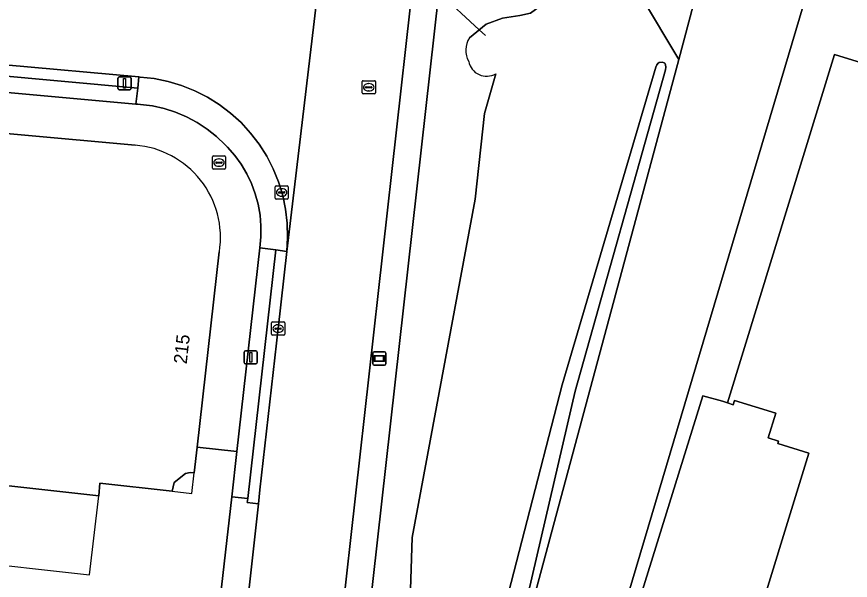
# Model space of a CAD drawing. Extents: x 161385 to 162589, y 388479 to 389756.
# Drawn here: x 162330.1 to 162393.2, y 388816.9 to 388859.6 of the extents above; entities that cross this region are included whole.
import ezdxf

# ---------------------------------------------------------------- set-up
doc = ezdxf.new("R2010")
doc.units = 0
for name, color, linetype in [('IMGEO_Berm_groen', 7, 'Continuous'), ('IMGEO_Duiker', 7, 'Continuous'), ('IMGEO_Erf', 7, 'Continuous'), ('IMGEO_Groenvoorziening', 7, 'Continuous'), ('IMGEO_Kolk', 7, 'Continuous'), ('IMGEO_Lichtmast', 7, 'Continuous'), ('IMGEO_Oever', 7, 'Continuous'), ('IMGEO_Pand', 7, 'Continuous'), ('IMGEO_Pand_nummerreeks', 7, 'Continuous'), ('IMGEO_Pand_overbouw', 7, 'Continuous'), ('IMGEO_Parkeervlak_open', 7, 'Continuous'), ('IMGEO_Rijbaan_lokaal_gesloten', 7, 'Continuous'), ('IMGEO_Rioolput', 7, 'Continuous'), ('IMGEO_Voetpad_open', 7, 'Continuous'), ('IMGEO_Waterloop', 7, 'Continuous'), ('IMGEO_Wegwijzer', 7, 'Continuous')]:
    doc.layers.add(name, color=color, linetype=linetype)

msp = doc.modelspace()

# ---------------------------------------------------------------- linework, layer by layer
at = {"layer": 'IMGEO_Berm_groen'}
for points in [[(162288.732, 388859.544), (162288.662, 388858.772), (162339.281, 388854.162), (162339.344, 388854.997)], [(162349.892, 388835.959), (162350.544, 388841.795), (162349.725, 388841.919), (162347.59, 388823.099), (162347.556, 388822.796), (162348.397, 388822.686), (162348.515, 388823.765)]]:
    msp.add_lwpolyline(points, close=True, dxfattribs=at)
at = {"layer": 'IMGEO_Duiker'}
msp.add_lwpolyline([(162365.584, 388858.13), (162365.112, 388858.568), (162362.048, 388861.405), (162360.956, 388862.417), (162360.209, 388863.109), (162355.382, 388867.663), (162353.656, 388867.925), (162352.651, 388868.077), (162346.541, 388869.005), (162345.729, 388869.128)], dxfattribs=at)
at = {"layer": 'IMGEO_Erf'}
for points in [[(162346.379, 388823.232), (162346.766, 388826.65), (162343.766, 388826.99), (162343.546, 388825.042), (162343.228, 388825.075), (162342.869, 388824.995), (162342.013, 388824.299), (162341.857, 388823.664), (162336.398, 388824.261), (162336.306, 388823.293), (162323.575, 388824.702)], [(162344.428, 388805.878), (162344.552, 388807.124), (162346.379, 388823.232)]]:
    msp.add_lwpolyline(points, dxfattribs=at)
at = {"layer": 'IMGEO_Groenvoorziening'}
for points in [[(162383.901, 388870.224), (162364.588, 388875.934), (162363.642, 388871.781), (162362.617, 388866.281), (162362.437, 388864.885), (162362.048, 388861.405), (162356.744, 388813.903)], [(162377.396, 388861.07), (162380.214, 388856.331), (162383.901, 388870.224)], [(162364.379, 388857.968), (162365.642, 388859.002), (162366.878, 388859.435), (162368.182, 388859.647), (162368.992, 388859.83), (162371.408, 388861.618)], [(162345.439, 388841.767), (162343.766, 388826.99), (162346.766, 388826.65), (162348.515, 388842.074), (162348.59, 388842.897), (162348.592, 388843.724), (162348.519, 388844.548), (162348.374, 388845.362), (162348.156, 388846.159), (162347.868, 388846.934), (162347.511, 388847.68), (162347.09, 388848.391), (162346.607, 388849.062), (162346.065, 388849.687), (162345.887, 388849.87), (162345.227, 388850.493), (162344.515, 388851.054), (162343.755, 388851.55), (162342.954, 388851.976), (162342.118, 388852.328), (162341.254, 388852.605), (162340.369, 388852.803), (162339.469, 388852.921), (162339.262, 388852.937), (162339.12, 388852.95), (162288.552, 388857.528)], [(162360.04, 388810.447), (162359.821, 388813.059), (162360.025, 388820.155), (162364.801, 388845.747), (162365.519, 388852.226), (162366.359, 388855.245)], [(162287.807, 388854.476), (162339.069, 388849.833)]]:
    msp.add_lwpolyline(points, dxfattribs=at)
for points in [[(162391.857, 388867.872), (162383.901, 388870.224), (162380.214, 388856.331), (162368.059, 388811.153), (162367.935, 388809.448), (162367.141, 388807.636), (162366.551, 388805.446), (162368.834, 388805.186), (162368.553, 388803.357), (162372.558, 388802.943)], [(162383.532, 388830.458), (162383.919, 388830.342), (162392.007, 388856.692), (162398.712, 388854.634), (162401.565, 388863.931), (162427.905, 388860.918), (162428.16, 388863.668), (162427.372, 388863.825), (162391.857, 388867.872), (162372.558, 388802.943), (162376.55, 388802.484), (162377.177, 388802.419), (162377.914, 388804.888), (162375.474, 388805.196), (162374.122, 388805.367), (162382.047, 388830.873)]]:
    msp.add_lwpolyline(points, close=True, dxfattribs=at)
for centre, radius, start, end in [((162365.796, 388857.018), 1.706, 146.16089, 209.96152), ((162365.665, 388856.428), 1.372, 191.02807, 300.39744), ((162338.526, 388842.856), 6.999, 351.05212, 85.54663)]:
    msp.add_arc(centre, radius, start, end, dxfattribs=at)
at = {"layer": 'IMGEO_Kolk'}
for p, q in [((162349.656, 388845.833), (162349.656, 388846.685)), ((162349.731, 388846.759), (162350.583, 388846.759)), ((162350.144, 388846.539), (162350.169, 388846.539)), ((162350.657, 388846.685), (162350.657, 388845.833)), ((162349.915, 388846.253), (162349.915, 388846.265)), ((162350.353, 388846.216), (162349.955, 388846.216)), ((162349.958, 388846.302), (162350.356, 388846.302)), ((162350.167, 388845.979), (162350.142, 388845.979)), ((162350.399, 388846.265), (162350.399, 388846.253)), ((162350.583, 388845.759), (162349.731, 388845.759)), ((162349.465, 388836.459), (162350.317, 388836.459)), ((162349.39, 388835.533), (162349.39, 388836.385)), ((162349.649, 388835.953), (162349.649, 388835.965)), ((162350.087, 388835.916), (162349.689, 388835.916)), ((162349.692, 388836.002), (162350.09, 388836.002)), ((162349.878, 388836.239), (162349.903, 388836.239)), ((162350.133, 388835.965), (162350.133, 388835.953)), ((162350.391, 388836.385), (162350.391, 388835.533)), ((162350.317, 388835.459), (162349.465, 388835.459)), ((162349.901, 388835.679), (162349.876, 388835.679))]:
    msp.add_line(p, q, dxfattribs=at)
for points in [[(162349.656, 388845.833), (162349.656, 388846.685)], [(162349.731, 388846.759), (162350.583, 388846.759)], [(162350.657, 388846.685), (162350.657, 388845.833)], [(162350.583, 388845.759), (162349.731, 388845.759)], [(162349.465, 388836.459), (162350.317, 388836.459)], [(162349.39, 388835.533), (162349.39, 388836.385)], [(162350.391, 388836.385), (162350.391, 388835.533)], [(162350.317, 388835.459), (162349.465, 388835.459)]]:
    msp.add_lwpolyline(points, dxfattribs=at)
for centre, radius, start, end in [((162349.733, 388846.683), 0.0765, 91.55205, 178.44795), ((162349.733, 388846.683), 0.0765, 91.55205, 178.44795), ((162350.581, 388846.683), 0.0765, 1.55205, 88.44795), ((162350.581, 388846.683), 0.0765, 1.55205, 88.44795), ((162349.955, 388846.262), 0.0403, 85.87752, 175.75265), ((162349.952, 388846.252), 0.0366, 178.93798, 274.71019), ((162350.356, 388846.259), 0.043, 264.86636, 352.45326), ((162350.36, 388846.264), 0.0386, 1.73085, 96.63898), ((162349.733, 388845.835), 0.0765, 181.55205, 268.44795), ((162349.733, 388845.835), 0.0765, 181.55205, 268.44795), ((162350.581, 388845.835), 0.0765, 271.55205, 358.44795), ((162350.581, 388845.835), 0.0765, 271.55205, 358.44795), ((162349.467, 388836.383), 0.0765, 91.55205, 178.44795), ((162349.467, 388836.383), 0.0765, 91.55205, 178.44795), ((162350.315, 388836.383), 0.0765, 1.55205, 88.44795), ((162350.315, 388836.383), 0.0765, 1.55205, 88.44795), ((162349.689, 388835.962), 0.0403, 85.87752, 175.75265), ((162349.686, 388835.952), 0.0366, 178.93798, 274.71019), ((162350.09, 388835.959), 0.043, 264.86636, 352.45326), ((162350.094, 388835.964), 0.0386, 1.73085, 96.63898), ((162349.467, 388835.535), 0.0765, 181.55205, 268.44795), ((162349.467, 388835.535), 0.0765, 181.55205, 268.44795), ((162350.315, 388835.535), 0.0765, 271.55205, 358.44795), ((162350.315, 388835.535), 0.0765, 271.55205, 358.44795)]:
    msp.add_arc(centre, radius, start, end, dxfattribs=at)
for centre, major_axis, ratio, start_param, end_param in [((162350.143, 388846.259), (-0.387, 0.002), 0.722429, 4.712389, 7.853982), ((162350.168, 388846.259), (-0.39, 0.002), 0.717154, 1.570796, 4.712389), ((162349.877, 388835.959), (-0.387, 0.002), 0.722429, 4.712389, 7.853982), ((162349.902, 388835.959), (-0.39, 0.002), 0.717154, 1.570796, 4.712389)]:
    msp.add_ellipse(centre, major_axis=major_axis, ratio=ratio, start_param=start_param, end_param=end_param, dxfattribs=at)
at = {"layer": 'IMGEO_Lichtmast'}
for p, q in [((162337.765, 388854.113), (162337.765, 388854.913)), ((162337.765, 388854.913), (162337.765, 388854.113)), ((162337.865, 388855.013), (162338.655, 388855.013)), ((162338.655, 388855.013), (162337.865, 388855.013)), ((162338.755, 388854.913), (162338.755, 388854.113)), ((162338.755, 388854.113), (162338.755, 388854.913)), ((162338.655, 388854.013), (162337.865, 388854.013)), ((162337.865, 388854.013), (162338.655, 388854.013)), ((162347.324, 388833.38), (162347.324, 388834.18)), ((162347.324, 388834.18), (162347.324, 388833.38)), ((162347.424, 388834.28), (162348.214, 388834.28)), ((162348.214, 388834.28), (162347.424, 388834.28)), ((162348.314, 388834.18), (162348.314, 388833.38)), ((162348.314, 388833.38), (162348.314, 388834.18)), ((162348.214, 388833.28), (162347.424, 388833.28)), ((162347.424, 388833.28), (162348.214, 388833.28))]:
    msp.add_line(p, q, dxfattribs=at)
for points in [[(162338.185, 388854.888), (162338.335, 388854.888), (162338.335, 388854.138), (162338.185, 388854.138), (162338.185, 388854.888)], [(162347.744, 388834.155), (162347.894, 388834.155), (162347.894, 388833.405), (162347.744, 388833.405), (162347.744, 388834.155)]]:
    msp.add_lwpolyline(points, dxfattribs=at)
for centre, start, end in [((162337.865, 388854.913), 90, 180), ((162337.865, 388854.913), 90, 180), ((162338.655, 388854.913), 0, 90), ((162338.655, 388854.913), 360, 90), ((162337.865, 388854.113), 180, 270), ((162337.865, 388854.113), 180, 270), ((162338.655, 388854.113), 270, 0), ((162338.655, 388854.113), 270, 0), ((162347.424, 388834.18), 90, 180), ((162347.424, 388834.18), 90, 180), ((162348.214, 388834.18), 0, 90), ((162348.214, 388834.18), 360, 90), ((162347.424, 388833.38), 180, 270), ((162347.424, 388833.38), 180, 270), ((162348.214, 388833.38), 270, 0), ((162348.214, 388833.38), 270, 0)]:
    msp.add_arc(centre, 0.1, start, end, dxfattribs=at)
at = {"layer": 'IMGEO_Oever'}
for points in [[(162371.408, 388861.618), (162368.992, 388859.83), (162368.182, 388859.647), (162366.878, 388859.435), (162365.642, 388859.002), (162364.379, 388857.968)], [(162380.214, 388856.331), (162377.396, 388861.07)], [(162362.622, 388807.156), (162365.602, 388806.733), (162367.141, 388807.636), (162367.935, 388809.448), (162368.059, 388811.153), (162380.214, 388856.331)], [(162366.359, 388855.245), (162365.519, 388852.226), (162364.801, 388845.747), (162360.025, 388820.155), (162359.821, 388813.059), (162360.04, 388810.447)]]:
    msp.add_lwpolyline(points, dxfattribs=at)
msp.add_lwpolyline([(162378.48, 388855.748), (162378.559, 388855.909), (162378.663, 388856.041), (162378.739, 388856.089), (162378.997, 388856.112), (162379.155, 388856.038), (162379.223, 388855.912), (162379.231, 388855.739), (162379.206, 388855.544), (162372.388, 388831.21), (162367.213, 388808.959), (162367.142, 388808.534), (162367.034, 388808.151), (162366.849, 388807.85), (162366.671, 388807.719), (162365.999, 388807.709), (162365.824, 388807.819), (162365.627, 388808.091), (162365.578, 388808.49), (162365.606, 388808.764), (162365.698, 388809.605), (162371.382, 388831.713)], close=True, dxfattribs=at)
for centre, radius, start, end in [((162365.796, 388857.018), 1.706, 146.16089, 209.96152), ((162365.665, 388856.428), 1.372, 191.02807, 300.39744)]:
    msp.add_arc(centre, radius, start, end, dxfattribs=at)
at = {"layer": 'IMGEO_Pand'}
for points in [[(162398.712, 388854.634), (162392.007, 388856.692), (162383.919, 388830.342), (162384.333, 388830.182), (162384.428, 388830.506), (162387.579, 388829.553), (162386.998, 388827.681), (162387.77, 388827.442), (162387.727, 388827.265), (162390.077, 388826.541), (162385.443, 388811.533), (162385.61, 388811.516), (162388.282, 388811.244), (162387.48, 388804.31), (162421.939, 388800.373)], [(162339.069, 388849.833), (162287.807, 388854.476), (162284.27, 388823.103), (162325.623, 388818.422), (162325.666, 388818.823), (162322.952, 388819.118), (162323.575, 388824.702), (162336.306, 388823.293), (162336.398, 388824.261), (162341.857, 388823.664), (162342.013, 388824.299), (162342.869, 388824.995), (162343.228, 388825.075), (162343.546, 388825.042), (162343.766, 388826.99), (162345.439, 388841.767)]]:
    msp.add_lwpolyline(points, dxfattribs=at)
msp.add_arc((162338.526, 388842.856), 6.999, 351.05212, 85.54663, dxfattribs=at)
at = {"layer": 'IMGEO_Pand_overbouw'}
for points in [[(162341.857, 388823.664), (162343.362, 388823.486), (162343.546, 388825.042), (162343.228, 388825.075), (162342.869, 388824.995), (162342.013, 388824.299)], [(162336.306, 388823.293), (162323.575, 388824.702), (162322.952, 388819.118), (162325.666, 388818.823), (162325.623, 388818.422), (162335.604, 388817.317)]]:
    msp.add_lwpolyline(points, close=True, dxfattribs=at)
at = {"layer": 'IMGEO_Parkeervlak_open'}
msp.add_lwpolyline([(162390.077, 388826.541), (162387.727, 388827.265), (162387.77, 388827.442), (162386.998, 388827.681), (162387.579, 388829.553), (162384.428, 388830.506), (162384.333, 388830.182), (162383.919, 388830.342), (162383.532, 388830.458), (162382.047, 388830.873), (162374.122, 388805.367), (162375.474, 388805.196), (162377.914, 388804.888), (162377.177, 388802.419), (162382.688, 388801.778), (162385.61, 388811.516), (162385.443, 388811.533)], close=True, dxfattribs=at)
at = {"layer": 'IMGEO_Rijbaan_lokaal_gesloten'}
for points in [[(162364.598, 388917.339), (162355.936, 388879.524), (162354.085, 388871.528), (162350.544, 388841.795), (162349.892, 388835.959), (162348.515, 388823.765), (162348.397, 388822.686), (162347.549, 388814.966), (162346.508, 388805.67), (162345.796, 388799.312), (162345.085, 388792.96), (162344.038, 388783.802), (162351.507, 388784.973), (162351.586, 388785.803), (162354.609, 388813.12), (162354.707, 388814.075), (162359.887, 388860.235), (162360.209, 388863.109), (162360.509, 388865.779), (162360.606, 388866.537), (162361.541, 388871.709), (162361.659, 388872.226), (162367.76, 388898.886)], [(162288.732, 388859.544), (162339.344, 388854.997), (162339.45, 388854.99), (162340.513, 388854.872), (162341.561, 388854.658), (162342.585, 388854.352), (162343.578, 388853.956), (162344.532, 388853.472), (162345.439, 388852.906), (162346.291, 388852.26), (162347.082, 388851.541), (162347.806, 388850.754), (162348.457, 388849.906), (162349.029, 388849.003), (162349.519, 388848.052), (162349.921, 388847.062), (162350.234, 388846.039), (162350.454, 388844.993), (162350.579, 388843.931), (162350.609, 388842.862), (162350.544, 388841.795), (162354.085, 388871.528)]]:
    msp.add_lwpolyline(points, dxfattribs=at)
at = {"layer": 'IMGEO_Rioolput'}
for p, q in [((162356.328, 388854.717), (162357.18, 388854.717)), ((162356.253, 388853.791), (162356.253, 388854.643)), ((162356.512, 388854.211), (162356.512, 388854.223)), ((162356.95, 388854.174), (162356.552, 388854.174)), ((162356.555, 388854.26), (162356.953, 388854.26)), ((162356.741, 388854.497), (162356.766, 388854.497)), ((162356.996, 388854.223), (162356.996, 388854.211)), ((162357.254, 388854.643), (162357.254, 388853.791)), ((162357.18, 388853.717), (162356.328, 388853.717)), ((162356.764, 388853.937), (162356.739, 388853.937)), ((162344.914, 388848.093), (162344.914, 388848.945)), ((162344.989, 388849.019), (162345.841, 388849.019)), ((162345.173, 388848.513), (162345.173, 388848.525)), ((162345.611, 388848.476), (162345.213, 388848.476)), ((162345.216, 388848.562), (162345.614, 388848.562)), ((162345.402, 388848.799), (162345.427, 388848.799)), ((162345.657, 388848.525), (162345.657, 388848.513)), ((162345.915, 388848.945), (162345.915, 388848.093)), ((162345.841, 388848.019), (162344.989, 388848.019)), ((162345.425, 388848.239), (162345.4, 388848.239))]:
    msp.add_line(p, q, dxfattribs=at)
for points in [[(162356.328, 388854.717), (162357.18, 388854.717)], [(162356.253, 388853.791), (162356.253, 388854.643)], [(162357.254, 388854.643), (162357.254, 388853.791)], [(162357.18, 388853.717), (162356.328, 388853.717)], [(162344.914, 388848.093), (162344.914, 388848.945)], [(162344.989, 388849.019), (162345.841, 388849.019)], [(162345.915, 388848.945), (162345.915, 388848.093)], [(162345.841, 388848.019), (162344.989, 388848.019)]]:
    msp.add_lwpolyline(points, dxfattribs=at)
for centre, radius, start, end in [((162356.33, 388854.641), 0.0765, 91.55205, 178.44795), ((162356.33, 388854.641), 0.0765, 91.55205, 178.44795), ((162357.178, 388854.641), 0.0765, 1.55205, 88.44795), ((162357.178, 388854.641), 0.0765, 1.55205, 88.44795), ((162356.552, 388854.22), 0.0403, 85.87752, 175.75265), ((162356.549, 388854.21), 0.0366, 178.93798, 274.71019), ((162356.953, 388854.217), 0.043, 264.86636, 352.45326), ((162356.957, 388854.222), 0.0386, 1.73085, 96.63898), ((162356.33, 388853.793), 0.0765, 181.55205, 268.44795), ((162356.33, 388853.793), 0.0765, 181.55205, 268.44795), ((162357.178, 388853.793), 0.0765, 271.55205, 358.44795), ((162357.178, 388853.793), 0.0765, 271.55205, 358.44795), ((162344.991, 388848.943), 0.0765, 91.55205, 178.44795), ((162344.991, 388848.943), 0.0765, 91.55205, 178.44795), ((162345.213, 388848.522), 0.0403, 85.87752, 175.75265), ((162345.21, 388848.512), 0.0366, 178.93798, 274.71019), ((162345.614, 388848.519), 0.043, 264.86636, 352.45326), ((162345.618, 388848.524), 0.0386, 1.73085, 96.63898), ((162345.839, 388848.943), 0.0765, 1.55205, 88.44795), ((162345.839, 388848.943), 0.0765, 1.55205, 88.44795), ((162344.991, 388848.095), 0.0765, 181.55205, 268.44795), ((162344.991, 388848.095), 0.0765, 181.55205, 268.44795), ((162345.839, 388848.095), 0.0765, 271.55205, 358.44795), ((162345.839, 388848.095), 0.0765, 271.55205, 358.44795)]:
    msp.add_arc(centre, radius, start, end, dxfattribs=at)
for centre, major_axis, ratio, start_param, end_param in [((162356.74, 388854.217), (-0.387, 0.002), 0.722429, 4.712389, 7.853982), ((162356.765, 388854.217), (-0.39, 0.002), 0.717154, 1.570796, 4.712389), ((162345.401, 388848.519), (-0.387, 0.002), 0.722429, 4.712389, 7.853982), ((162345.426, 388848.519), (-0.39, 0.002), 0.717154, 1.570796, 4.712389)]:
    msp.add_ellipse(centre, major_axis=major_axis, ratio=ratio, start_param=start_param, end_param=end_param, dxfattribs=at)
at = {"layer": 'IMGEO_Voetpad_open'}
for points in [[(162362.048, 388861.405), (162362.437, 388864.885), (162362.617, 388866.281), (162363.642, 388871.781), (162364.588, 388875.934), (162369.717, 388898.438), (162368.533, 388898.709), (162362.453, 388872.044), (162361.659, 388872.226), (162361.541, 388871.709), (162360.606, 388866.537), (162360.509, 388865.779), (162360.209, 388863.109), (162359.887, 388860.235), (162354.707, 388814.075), (162356.744, 388813.903)], [(162288.662, 388858.772), (162288.552, 388857.528), (162339.12, 388852.95), (162339.281, 388854.162)], [(162339.281, 388854.162), (162339.12, 388852.95), (162339.262, 388852.937), (162339.469, 388852.921), (162340.369, 388852.803), (162341.254, 388852.605), (162342.118, 388852.328), (162342.954, 388851.976), (162343.755, 388851.55), (162344.515, 388851.054), (162345.227, 388850.493), (162345.887, 388849.87), (162346.065, 388849.687), (162346.607, 388849.062), (162347.09, 388848.391), (162347.511, 388847.68), (162347.868, 388846.934), (162348.156, 388846.159), (162348.374, 388845.362), (162348.519, 388844.548), (162348.592, 388843.724), (162348.59, 388842.897), (162348.515, 388842.074), (162349.725, 388841.919), (162350.544, 388841.795), (162350.609, 388842.862), (162350.579, 388843.931), (162350.454, 388844.993), (162350.234, 388846.039), (162349.921, 388847.062), (162349.519, 388848.052), (162349.029, 388849.003), (162348.457, 388849.906), (162347.806, 388850.754), (162347.082, 388851.541), (162346.291, 388852.26), (162345.439, 388852.906), (162344.532, 388853.472), (162343.578, 388853.956), (162342.585, 388854.352), (162341.561, 388854.658), (162340.513, 388854.872), (162339.45, 388854.99), (162339.344, 388854.997)], [(162346.379, 388823.232), (162347.59, 388823.099), (162349.725, 388841.919), (162348.515, 388842.074), (162346.766, 388826.65)], [(162343.72, 388799.552), (162344.909, 388799.405), (162345.796, 388799.312), (162346.508, 388805.67), (162347.549, 388814.966), (162348.397, 388822.686), (162347.556, 388822.796), (162347.59, 388823.099), (162346.379, 388823.232), (162344.552, 388807.124), (162344.428, 388805.878)]]:
    msp.add_lwpolyline(points, close=True, dxfattribs=at)
at = {"layer": 'IMGEO_Waterloop'}
msp.add_lwpolyline([(162379.206, 388855.544), (162379.231, 388855.739), (162379.223, 388855.912), (162379.155, 388856.038), (162378.997, 388856.112), (162378.739, 388856.089), (162378.663, 388856.041), (162378.559, 388855.909), (162378.48, 388855.748), (162371.382, 388831.713), (162365.698, 388809.605), (162365.606, 388808.764), (162365.578, 388808.49), (162365.627, 388808.091), (162365.824, 388807.819), (162365.999, 388807.709), (162366.671, 388807.719), (162366.849, 388807.85), (162367.034, 388808.151), (162367.142, 388808.534), (162367.213, 388808.959), (162372.388, 388831.21)], close=True, dxfattribs=at)
at = {"layer": 'IMGEO_Wegwijzer'}
for p, q in [((162357.049, 388833.297), (162357.049, 388834.097)), ((162357.049, 388834.097), (162357.049, 388833.297)), ((162357.149, 388834.197), (162357.939, 388834.197)), ((162357.939, 388834.197), (162357.149, 388834.197)), ((162358.039, 388834.097), (162358.039, 388833.297)), ((162358.039, 388833.297), (162358.039, 388834.097)), ((162357.939, 388833.197), (162357.149, 388833.197)), ((162357.149, 388833.197), (162357.939, 388833.197))]:
    msp.add_line(p, q, dxfattribs=at)
for points in [[(162357.15, 388833.929), (162357.938, 388833.929), (162357.938, 388833.465), (162357.15, 388833.465), (162357.15, 388833.929)], [(162357.215, 388833.864), (162357.215, 388833.53), (162357.873, 388833.53), (162357.873, 388833.864), (162357.215, 388833.864)]]:
    msp.add_lwpolyline(points, dxfattribs=at)
for centre, start, end in [((162357.149, 388834.097), 90, 180), ((162357.149, 388834.097), 90, 180), ((162357.939, 388834.097), 0, 90), ((162357.939, 388834.097), 360, 90), ((162357.149, 388833.297), 180, 270), ((162357.149, 388833.297), 180, 270), ((162357.939, 388833.297), 270, 0), ((162357.939, 388833.297), 270, 0)]:
    msp.add_arc(centre, 0.1, start, end, dxfattribs=at)

# ---------------------------------------------------------------- texts
at = {"layer": 'IMGEO_Pand_nummerreeks'}
msp.add_text('215', height=1, rotation=83.54298, dxfattribs=at).set_placement((162342.965, 388833.243))

doc.saveas('drawing.dxf')
